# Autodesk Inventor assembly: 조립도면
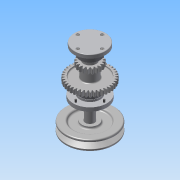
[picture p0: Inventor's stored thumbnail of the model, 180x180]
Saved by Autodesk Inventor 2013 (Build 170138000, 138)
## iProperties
Created: 2016-01
Part Number: 조립도면
Document SubType Name: Assembly
Designer: mrc
Author: mrc
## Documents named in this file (13)
- C:\Users\mrc\Desktop\460106V1023\460106V1023\조립도면.iam
- C:\Users\mrc\Desktop\460106V1023\본체.ipt
- C:\Users\mrc\Desktop\460106V1023\460106V1023\축.ipt
- C:\Users\mrc\Desktop\460106V1023\460106V1023\V-벨트풀리.ipt
- C:\Users\mrc\Desktop\460106V1023\460106V1023\뒤커버.ipt
- C:\Users\mrc\Desktop\460106V1023\460106V1023\앞커버.ipt
- C:\Users\mrc\Desktop\460106V1023\460106V1023\볼트 M3 x 8.ipt
- C:\Users\mrc\Desktop\460106V1023\460106V1023\볼트 M3 x 10.ipt
- C:\Users\mrc\Desktop\460106V1023\460106V1023\키 - 6 x 6 x 22.ipt
- C:\Users\mrc\Desktop\460106V1023\460106V1023\키 - 5 x 5 x 18.ipt
- C:\Users\mrc\Desktop\460106V1023\460106V1023\베어링 6203.ipt
- C:\Users\mrc\Desktop\460106V1023\460106V1023\부시1.ipt
- C:\Users\mrc\Desktop\460106V1023\460106V1023\스퍼기어.ipt
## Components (9 placed, 3 different names)
1. V-벨트풀리:1
2. ISO 4762 M3 x 8:2
3. ISO 4762 M3 x 8:3
4. ISO 4762 M3 x 8:4
5. ISO 4762 M3 x 8:5
6. ISO 4762 M3 x 10:1
7. ISO 4762 M3 x 10:2
8. ISO 4762 M3 x 10:3
9. ISO 4762 M3 x 10:4
